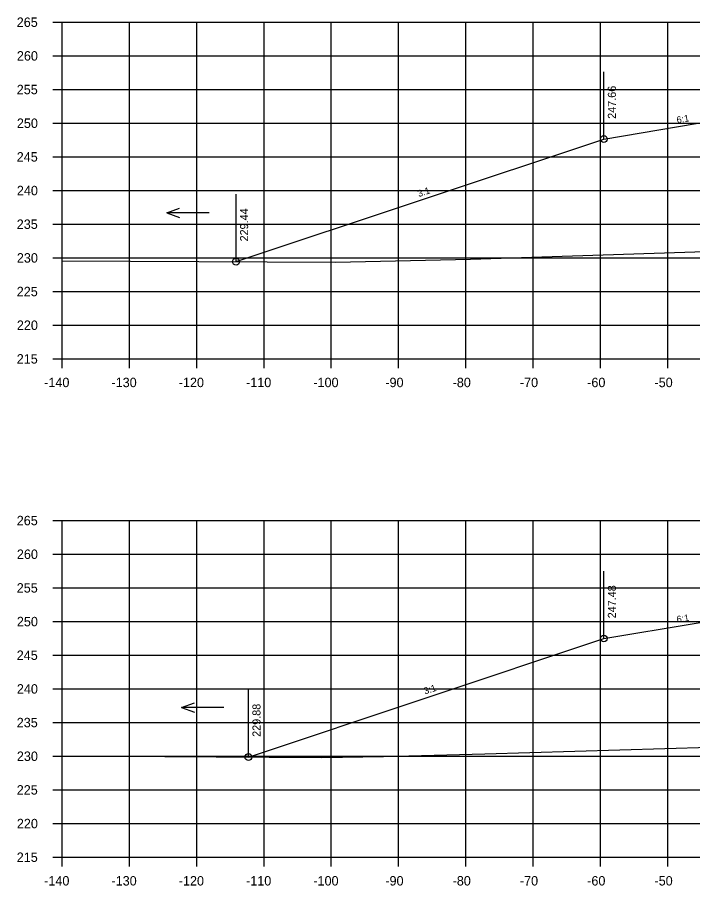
# Model space of a CAD drawing. Extents: x 1342547 to 1344156, y -1532351 to -1517216.
# Drawn here: x 1342556.2 to 1342656.6, y -1524015.2 to -1523886.2 of the extents above; entities that cross this region are included whole.
import ezdxf

# ---------------------------------------------------------------- set-up
doc = ezdxf.new("R2010")
doc.units = 0
for name, color, linetype in [('R_Axis', 7, 'Continuous'), ('R_Axis Annot', 7, 'Continuous'), ('R_Exist Surface', 7, 'Continuous'), ('R_Fin Surface', 7, 'Continuous'), ('R_Grid', 7, 'Continuous'), ('R_No Plot', 7, 'Continuous'), ('R_Water', 7, 'Continuous'), ('R_Xsect Elev', 7, 'Continuous'), ('R_Xsect Slope', 7, 'Continuous')]:
    doc.layers.add(name, color=color, linetype=linetype)

msp = doc.modelspace()

# ---------------------------------------------------------------- linework, layer by layer
at = {"layer": 'R_Axis'}
for p, q in [((1342561.47, -1523886.96), (1342562.87, -1523886.96)), ((1342562.87, -1523936.96), (1342562.87, -1523886.96)), ((1342561.47, -1523891.96), (1342562.87, -1523891.96)), ((1342561.47, -1523896.96), (1342562.87, -1523896.96)), ((1342561.47, -1523901.96), (1342562.87, -1523901.96)), ((1342561.47, -1523906.96), (1342562.87, -1523906.96)), ((1342561.47, -1523911.96), (1342562.87, -1523911.96)), ((1342561.47, -1523916.96), (1342562.87, -1523916.96)), ((1342561.47, -1523921.96), (1342562.87, -1523921.96)), ((1342561.47, -1523926.96), (1342562.87, -1523926.96)), ((1342561.47, -1523931.96), (1342562.87, -1523931.96)), ((1342561.47, -1523936.96), (1342562.87, -1523936.96)), ((1342562.87, -1523936.96), (1342842.87, -1523936.96)), ((1342562.87, -1523938.36), (1342562.87, -1523936.96)), ((1342572.87, -1523938.36), (1342572.87, -1523936.96)), ((1342582.87, -1523938.36), (1342582.87, -1523936.96)), ((1342592.87, -1523938.36), (1342592.87, -1523936.96)), ((1342602.87, -1523938.36), (1342602.87, -1523936.96)), ((1342612.87, -1523938.36), (1342612.87, -1523936.96)), ((1342622.87, -1523938.36), (1342622.87, -1523936.96)), ((1342632.87, -1523938.36), (1342632.87, -1523936.96)), ((1342642.87, -1523938.36), (1342642.87, -1523936.96)), ((1342652.87, -1523938.36), (1342652.87, -1523936.96)), ((1342561.47, -1523960.97), (1342562.87, -1523960.97)), ((1342562.87, -1524010.97), (1342562.87, -1523960.97)), ((1342561.47, -1523965.97), (1342562.87, -1523965.97)), ((1342561.47, -1523970.97), (1342562.87, -1523970.97)), ((1342561.47, -1523975.97), (1342562.87, -1523975.97)), ((1342561.47, -1523980.97), (1342562.87, -1523980.97)), ((1342561.47, -1523985.97), (1342562.87, -1523985.97)), ((1342561.47, -1523990.97), (1342562.87, -1523990.97)), ((1342561.47, -1523995.97), (1342562.87, -1523995.97)), ((1342561.47, -1524000.97), (1342562.87, -1524000.97)), ((1342561.47, -1524005.97), (1342562.87, -1524005.97)), ((1342561.47, -1524010.97), (1342562.87, -1524010.97)), ((1342562.87, -1524010.97), (1342842.87, -1524010.97)), ((1342562.87, -1524012.37), (1342562.87, -1524010.97)), ((1342572.87, -1524012.37), (1342572.87, -1524010.97)), ((1342582.87, -1524012.37), (1342582.87, -1524010.97)), ((1342592.87, -1524012.37), (1342592.87, -1524010.97)), ((1342602.87, -1524012.37), (1342602.87, -1524010.97)), ((1342612.87, -1524012.37), (1342612.87, -1524010.97)), ((1342622.87, -1524012.37), (1342622.87, -1524010.97)), ((1342632.87, -1524012.37), (1342632.87, -1524010.97)), ((1342642.87, -1524012.37), (1342642.87, -1524010.97)), ((1342652.87, -1524012.37), (1342652.87, -1524010.97))]:
    msp.add_line(p, q, dxfattribs=at)
at = {"layer": 'R_Exist Surface'}
for points in [[(1342562.87, -1523922.38), (1342603.48, -1523922.61), (1342623.55, -1523922.15), (1342658.43, -1523921.01), (1342667.15, -1523919.72), (1342675.04, -1523918.1)], [(1342562.87, -1523995.92), (1342585.77, -1523996.06), (1342601.44, -1523996.16), (1342610.65, -1523996.03), (1342625.69, -1523995.62), (1342659.15, -1523994.64), (1342671.19, -1523992.17)]]:
    msp.add_lwpolyline(points, dxfattribs=at)
at = {"layer": 'R_Fin Surface'}
for points in [[(1342588.71, -1523922.52), (1342643.37, -1523904.31), (1342657.09, -1523902.02), (1342665.37, -1523900.64), (1342671.37, -1523900.4), (1342673.37, -1523900.36), (1342702.87, -1523899.77), (1342732.37, -1523900.36), (1342734.37, -1523900.4), (1342746.12, -1523900.87)], [(1342590.55, -1523996.09), (1342643.37, -1523978.49), (1342657.09, -1523976.2), (1342665.37, -1523974.82), (1342671.37, -1523974.58), (1342673.37, -1523974.54), (1342702.87, -1523973.95), (1342732.37, -1523974.54), (1342734.37, -1523974.58), (1342745.87, -1523975.04)]]:
    msp.add_lwpolyline(points, dxfattribs=at)
at = {"layer": 'R_Grid'}
for p, q in [((1342562.87, -1523886.96), (1342842.87, -1523886.96)), ((1342562.87, -1523936.96), (1342562.87, -1523886.96)), ((1342572.87, -1523936.96), (1342572.87, -1523886.96)), ((1342582.87, -1523936.96), (1342582.87, -1523886.96)), ((1342592.87, -1523936.96), (1342592.87, -1523886.96)), ((1342602.87, -1523936.96), (1342602.87, -1523886.96)), ((1342612.87, -1523936.96), (1342612.87, -1523886.96)), ((1342622.87, -1523936.96), (1342622.87, -1523886.96)), ((1342632.87, -1523936.96), (1342632.87, -1523886.96)), ((1342642.87, -1523936.96), (1342642.87, -1523886.96)), ((1342652.87, -1523936.96), (1342652.87, -1523886.96)), ((1342562.87, -1523891.96), (1342842.87, -1523891.96)), ((1342562.87, -1523896.96), (1342842.87, -1523896.96)), ((1342562.87, -1523901.96), (1342842.87, -1523901.96)), ((1342562.87, -1523906.96), (1342842.87, -1523906.96)), ((1342562.87, -1523911.96), (1342842.87, -1523911.96)), ((1342562.87, -1523916.96), (1342842.87, -1523916.96)), ((1342562.87, -1523921.96), (1342842.87, -1523921.96)), ((1342562.87, -1523926.96), (1342842.87, -1523926.96)), ((1342562.87, -1523931.96), (1342842.87, -1523931.96)), ((1342562.87, -1523936.96), (1342842.87, -1523936.96)), ((1342562.87, -1523960.97), (1342842.87, -1523960.97)), ((1342562.87, -1524010.97), (1342562.87, -1523960.97)), ((1342572.87, -1524010.97), (1342572.87, -1523960.97)), ((1342582.87, -1524010.97), (1342582.87, -1523960.97)), ((1342592.87, -1524010.97), (1342592.87, -1523960.97)), ((1342602.87, -1524010.97), (1342602.87, -1523960.97)), ((1342612.87, -1524010.97), (1342612.87, -1523960.97)), ((1342622.87, -1524010.97), (1342622.87, -1523960.97)), ((1342632.87, -1524010.97), (1342632.87, -1523960.97)), ((1342642.87, -1524010.97), (1342642.87, -1523960.97)), ((1342652.87, -1524010.97), (1342652.87, -1523960.97)), ((1342562.87, -1523965.97), (1342842.87, -1523965.97)), ((1342562.87, -1523970.97), (1342842.87, -1523970.97)), ((1342562.87, -1523975.97), (1342842.87, -1523975.97)), ((1342562.87, -1523980.97), (1342842.87, -1523980.97)), ((1342562.87, -1523985.97), (1342842.87, -1523985.97)), ((1342562.87, -1523990.97), (1342842.87, -1523990.97)), ((1342562.87, -1523995.97), (1342842.87, -1523995.97)), ((1342562.87, -1524000.97), (1342842.87, -1524000.97)), ((1342562.87, -1524005.97), (1342842.87, -1524005.97)), ((1342562.87, -1524010.97), (1342842.87, -1524010.97))]:
    msp.add_line(p, q, dxfattribs=at)
at = {"layer": 'R_No Plot'}
for centre in [(1342643.37, -1523904.31), (1342588.71, -1523922.52), (1342643.37, -1523978.49), (1342590.55, -1523996.09)]:
    msp.add_circle(centre, 0.5, dxfattribs=at)
at = {"layer": 'R_Water'}
for p, q in [((1342578.41, -1523915.27), (1342580.33, -1523914.57)), ((1342584.7, -1523915.27), (1342578.41, -1523915.27)), ((1342578.41, -1523915.27), (1342580.33, -1523915.97)), ((1342580.61, -1523988.72), (1342582.54, -1523988.02)), ((1342586.9, -1523988.72), (1342580.61, -1523988.72)), ((1342580.61, -1523988.72), (1342582.54, -1523989.42))]:
    msp.add_line(p, q, dxfattribs=at)
at = {"layer": 'R_Xsect Elev'}
for p, q in [((1342643.37, -1523904.31), (1342643.37, -1523894.31)), ((1342588.71, -1523922.52), (1342588.71, -1523912.52)), ((1342643.37, -1523978.49), (1342643.37, -1523968.49)), ((1342590.55, -1523996.09), (1342590.55, -1523986.09))]:
    msp.add_line(p, q, dxfattribs=at)

# ---------------------------------------------------------------- texts
at = {"layer": 'R_Axis Annot'}
for s, p in [('265', (1342556.12, -1523887.66)), ('260', (1342556.14, -1523892.66)), ('255', (1342556.12, -1523897.66)), ('250', (1342556.14, -1523902.66)), ('245', (1342556.12, -1523907.66)), ('240', (1342556.14, -1523912.66)), ('235', (1342556.12, -1523917.66)), ('230', (1342556.14, -1523922.66)), ('225', (1342556.12, -1523927.66)), ('220', (1342556.14, -1523932.66)), ('215', (1342556.12, -1523937.66)), ('-140', (1342560.2, -1523941.16)), ('-130', (1342570.2, -1523941.16)), ('-120', (1342580.2, -1523941.16)), ('-110', (1342590.2, -1523941.16)), ('-100', (1342600.2, -1523941.16)), ('-90', (1342610.9, -1523941.16)), ('-80', (1342620.9, -1523941.16)), ('-70', (1342630.9, -1523941.16)), ('-60', (1342640.9, -1523941.16)), ('-50', (1342650.9, -1523941.16)), ('265', (1342556.12, -1523961.67)), ('260', (1342556.14, -1523966.67)), ('255', (1342556.12, -1523971.67)), ('250', (1342556.14, -1523976.67)), ('245', (1342556.12, -1523981.67)), ('240', (1342556.14, -1523986.67)), ('235', (1342556.12, -1523991.67)), ('230', (1342556.14, -1523996.67)), ('225', (1342556.12, -1524001.67)), ('220', (1342556.14, -1524006.67)), ('215', (1342556.12, -1524011.67)), ('-140', (1342560.2, -1524015.17)), ('-130', (1342570.2, -1524015.17)), ('-120', (1342580.2, -1524015.17)), ('-110', (1342590.2, -1524015.17)), ('-100', (1342600.2, -1524015.17)), ('-90', (1342610.9, -1524015.17)), ('-80', (1342620.9, -1524015.17)), ('-70', (1342630.9, -1524015.17)), ('-60', (1342640.9, -1524015.17)), ('-50', (1342650.9, -1524015.17))]:
    msp.add_text(s, height=1.4, dxfattribs=at).set_placement(p)
at = {"layer": 'R_Xsect Elev'}
for s, p in [('247.66', (1342645.17, -1523901.31)), ('229.44', (1342590.51, -1523919.52)), ('247.48', (1342645.17, -1523975.49)), ('229.88', (1342592.35, -1523993.09))]:
    msp.add_text(s, height=1.2, rotation=90, dxfattribs=at).set_placement(p)
at = {"layer": 'R_Xsect Slope'}
for s, rotation, p in [('6:1', 9.4623, (1342654.28, -1523901.98)), ('3:1', 18.4349, (1342615.88, -1523912.94)), ('6:1', 9.4623, (1342654.28, -1523976.16)), ('3:1', 18.4349, (1342616.8, -1523986.81))]:
    msp.add_text(s, height=1, rotation=rotation, dxfattribs=at).set_placement(p)

doc.saveas('drawing.dxf')
